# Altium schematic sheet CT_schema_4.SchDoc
size 288 x 169 mm
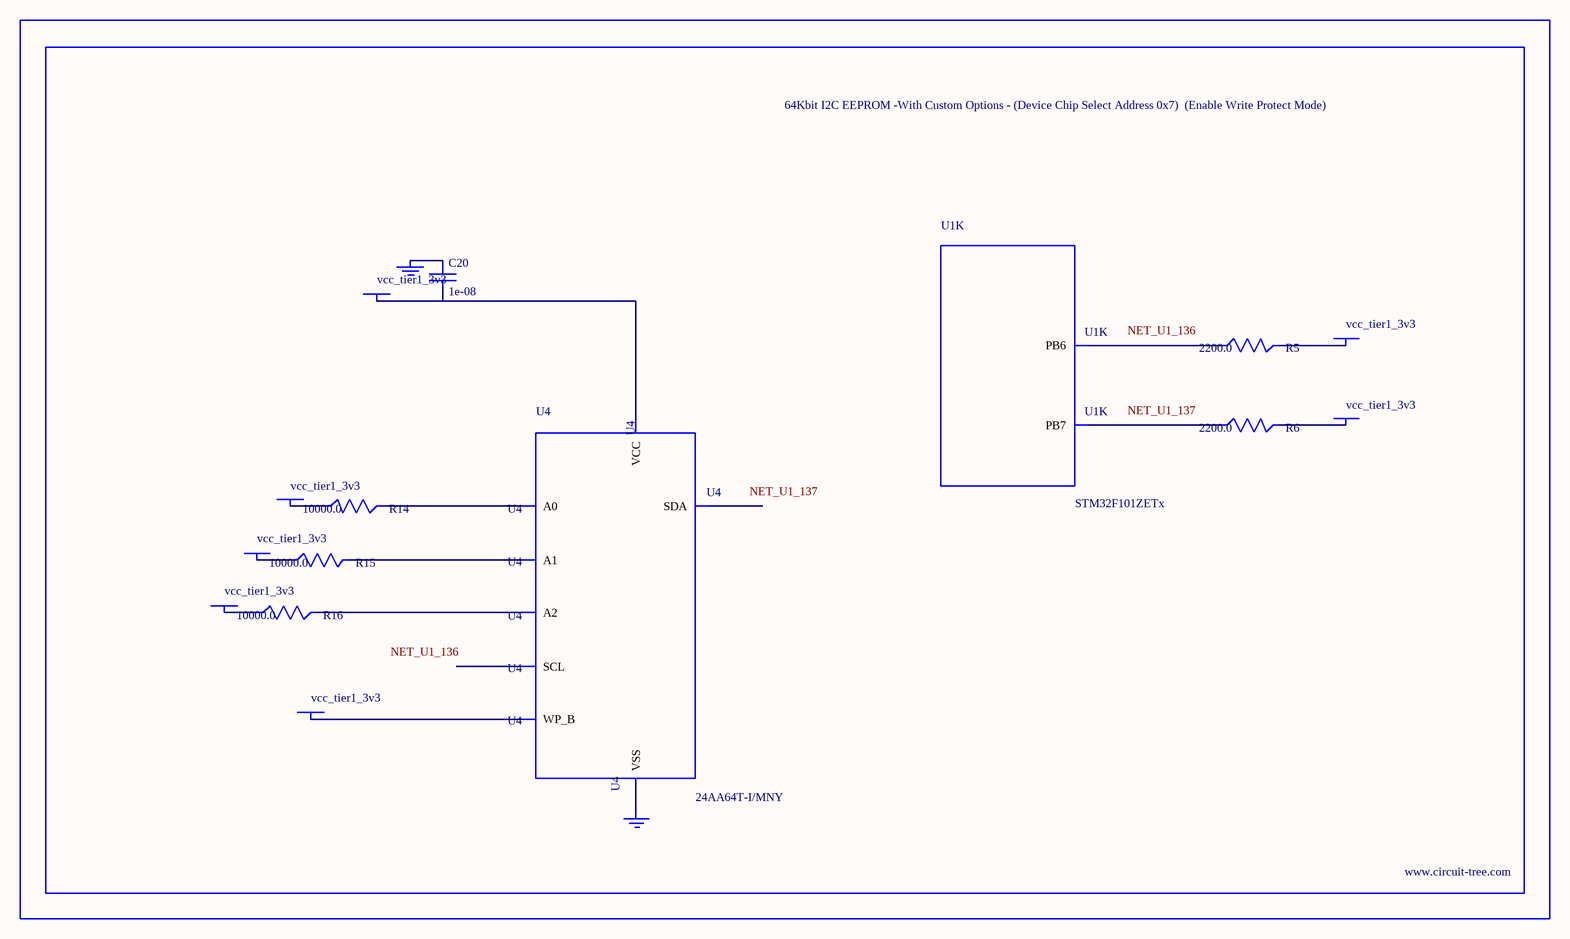
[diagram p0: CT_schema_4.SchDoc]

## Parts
BORDER3  (no value)
C20  1e-08  [C0402]
GND_INSTANCE_3_0  (no value)
GND_INSTANCE_3_1  (no value)
POWER_INSTANCE_3_0  vcc_tier1_3v3
POWER_INSTANCE_3_1  vcc_tier1_3v3
POWER_INSTANCE_3_2  vcc_tier1_3v3
POWER_INSTANCE_3_3  vcc_tier1_3v3
POWER_INSTANCE_3_4  vcc_tier1_3v3
POWER_INSTANCE_3_5  vcc_tier1_3v3
POWER_INSTANCE_3_6  vcc_tier1_3v3
R5  2200.0  [R0603]
R6  2200.0  [R0603]
R14  10000.0  [R0603]
R15  10000.0  [R0603]
R16  10000.0  [R0603]
U1  STM32F101ZETx  [LQFP144]  (part K of 12)
U4  24AA64T-I/MNY  [TDFN-8/6MM]

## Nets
NetC20_1: C20.1 GND_INSTANCE_3_0.0(GND)
NetC20_2: C20.2 POWER_INSTANCE_3_4.0(PWR) U4.8(VCC)
NetGND_INSTANCE_3_1_0: GND_INSTANCE_3_1.0(GND) U4.4(VSS)
NetPOWER_INSTANCE_3_0_0: POWER_INSTANCE_3_0.0(PWR) R14.1
NetPOWER_INSTANCE_3_1_0: POWER_INSTANCE_3_1.0(PWR) R15.1
NetPOWER_INSTANCE_3_2_0: POWER_INSTANCE_3_2.0(PWR) R16.1
NetPOWER_INSTANCE_3_3_0: POWER_INSTANCE_3_3.0(PWR) U4.7(WP_B)
NetPOWER_INSTANCE_3_5_0: POWER_INSTANCE_3_5.0(PWR) R5.2
NetPOWER_INSTANCE_3_6_0: POWER_INSTANCE_3_6.0(PWR) R6.2
NetR5_1: R5.1 U1.136(PB6)
NetR6_1: R6.1 U1.137(PB7)
NetR14_2: R14.2 U4.1(A0)
NetR15_2: R15.2 U4.2(A1)
NetR16_2: R16.2 U4.3(A2)

Not connected (* = marked no-connect by the designer): U4 5(SDA) 6(SCL)

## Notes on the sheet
- Labels drawn without touching a wire or pin: NET_U1_136, NET_U1_137

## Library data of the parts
BORDER3 = BORDER_PAGE3
C20 = C0402C103K3RAC
GND_INSTANCE_3_0 GND_INSTANCE_3_1 = GND
POWER_INSTANCE_3_0-POWER_INSTANCE_3_6 = PWR
R5 R6 = RC0603JR-072K2L
R14-R16 = RC0603JR-0710KL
